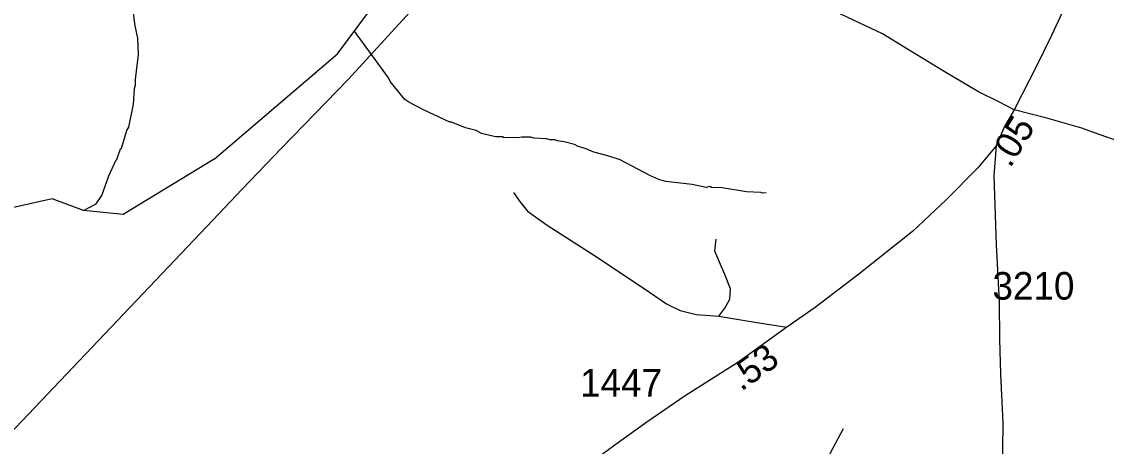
# Model space of a CAD drawing. Extents: x 1547597 to 1699558, y 810033 to 920809.
# Drawn here: x 1593314 to 1598233, y 880561 to 882486 of the extents above; entities that cross this region are included whole.
import ezdxf

# ---------------------------------------------------------------- set-up
doc = ezdxf.new("R2010")
doc.units = 0
for name, color, linetype in [('Exist Hydrographic Creek Single Shore', 7, 'Continuous'), ('Exist Hydrographic Misc Water Feature', 7, 'Continuous'), ('Exist Road Non-System Type 51', 7, 'Continuous'), ('Exist Road Secondary Mileage Hundredths English Label', 7, 'Continuous'), ('Exist Road Secondary Type 51 Attributed', 7, 'Continuous'), ('Exist Road Secondary Type 51 Number Label', 7, 'Continuous'), ('Exist Utilities Electrical Transmission Line', 7, 'Continuous')]:
    doc.layers.add(name, color=color, linetype=linetype)

msp = doc.modelspace()

# ---------------------------------------------------------------- linework, layer by layer
at = {"layer": 'Exist Hydrographic Creek Single Shore'}
for points in [[(1594187.7, 881861.8), (1594746.6, 882339.6), (1594983.6, 882659.8), (1595044.6, 882819.4), (1595315.6, 883138.9), (1595428.6, 883487.9), (1595969.1, 884179.6), (1596114.7, 884695.1), (1596193.9, 885183.4), (1596366.1, 885799.3), (1596375.1, 886314.1)], [(1594187.7, 881861.8), (1593774.6, 881610.9), (1593594.9, 881630.2), (1593452.5, 881682.2), (1592972.6, 881575.9), (1592470.6, 881427.1), (1591866.6, 881163.7), (1591683.6, 881190.4), (1591526.6, 881259.2), (1591117.8, 881560.8), (1590746.3, 882107), (1590660.1, 882244.9), (1590503.1, 882356.4), (1590267.6, 882420.6), (1589867.3, 882354.7)], [(1596667.6, 879444.6), (1596649.4, 879560), (1596571.5, 879569.7), (1596547.1, 879764.6), (1596595.8, 879871.9), (1596683.6, 880071.2), (1596921.6, 880417.7), (1597041.6, 880641.8)]]:
    msp.add_lwpolyline(points, dxfattribs=at)
at = {"layer": 'Exist Hydrographic Misc Water Feature'}
for points in [[(1593594.9, 881630.2), (1593651.5, 881659.7), (1593677.9, 881697.3), (1593709.1, 881786.5), (1593741.5, 881856.4), (1593745.9, 881860.4), (1593761.6, 881908.6), (1593766.6, 881912.2), (1593791.5, 881991.9), (1593799.7, 882007.8), (1593820.9, 882111.4), (1593825.9, 882183.4), (1593830.1, 882199.4), (1593830.4, 882223.4), (1593844.4, 882336.2), (1593840.6, 882411.2), (1593829.2, 882467.4), (1593818.3, 882547.4), (1593802.9, 882603.6), (1593795.6, 882657.8), (1593794.2, 882703.8), (1593784.5, 882739.9), (1593783.5, 882779.2)], [(1596690, 881709.6), (1596673.9, 881707.9), (1596666, 881712), (1596602.1, 881715), (1596490.4, 881733), (1596442.5, 881733.8), (1596434.5, 881737.9), (1596418.5, 881734.1), (1596354.8, 881747.2), (1596235, 881761.3), (1596203.1, 881769.8), (1596163.5, 881788.4), (1596028.7, 881858.7), (1595973.1, 881877.6), (1595909.3, 881894.8), (1595869.6, 881911.4), (1595837.7, 881919.9), (1595821.9, 881928.2), (1595774.2, 881941), (1595742.2, 881945.5), (1595734.3, 881949.6), (1595710.3, 881950), (1595694.4, 881954.3), (1595638.4, 881957.3), (1595622.5, 881961.5), (1595582.5, 881962.2), (1595566.5, 881958.5), (1595558.6, 881960.6), (1595502.6, 881959.6), (1595494.7, 881963.7), (1595462.7, 881964.3), (1595398.9, 881979.4), (1595375.1, 881991.8), (1595327.4, 882004.5), (1595263.8, 882029.6), (1595255.8, 882029.7), (1595136.8, 882085.7), (1595069.3, 882120.8), (1595051.6, 882133.1), (1594984.9, 882214.2), (1594977.1, 882230.4), (1594823.1, 882443)]]:
    msp.add_lwpolyline(points, dxfattribs=at)
at = {"layer": 'Exist Road Non-System Type 51'}
for points in [[(1595544.8, 881710.6), (1595572.5, 881672.3), (1595607.9, 881626.1), (1595697.5, 881563.2), (1595912.2, 881425.6), (1596136.9, 881275.8), (1596238.2, 881206.9), (1596300, 881176.4), (1596373.7, 881157.9), (1596475.6, 881151)], [(1596475.6, 881151), (1596503.9, 881186.7), (1596526.2, 881227.4), (1596528.5, 881274.6), (1596503.2, 881338.8), (1596479.5, 881394.9), (1596458, 881445.1), (1596464.5, 881499)], [(1596475.6, 881151), (1596639.3, 881123.7), (1596785.1, 881100.5)]]:
    msp.add_lwpolyline(points, dxfattribs=at)
at = {"layer": 'Exist Road Secondary Type 51 Attributed'}
for points in [[(1598138.2, 883928.7), (1598144.3, 883785.9), (1598140.2, 883600.3), (1598144.3, 883451.3), (1598154.5, 883265), (1598152.9, 883049.1), (1598134.2, 882837.2), (1598117.9, 882739.3), (1598074.4, 882616.2), (1597985, 882423.1), (1597918.8, 882287), (1597816.2, 882086.1)], [(1597816.2, 882086.1), (1597745.7, 882122.2), (1597653.9, 882167), (1597505.1, 882254.8), (1597331.9, 882360.9), (1597217.7, 882430.2), (1596981.3, 882542.4), (1596740.2, 882657.9), (1596454.8, 882755.9), (1596253, 882817.1), (1596026.8, 882900.7), (1595814.2, 882993.1), (1595566.3, 883084.8), (1595402.4, 883133.3), (1595203.1, 883202.3), (1595061.2, 883244.5), (1594919.4, 883290.5), (1594772.1, 883371.1)], [(1597816.2, 882086.1), (1597772.2, 882010.5), (1597734.2, 881922.2)], [(1600730.5, 880607), (1600618.4, 880660.1), (1600532.8, 880707), (1600402.4, 880804.9), (1600235.2, 880927.3), (1600139.4, 881025.2), (1600021.2, 881121.1), (1599941.7, 881178.2), (1599838.9, 881253.2), (1599659.5, 881375.6), (1599474.7, 881470.8), (1599301.4, 881562.6), (1599193.5, 881617.5), (1598959.3, 881729.3), (1598692.2, 881811.1), (1598451.7, 881884.6), (1598288.6, 881943.7), (1598196.9, 881976.3), (1598122.1, 882002.9), (1597963.1, 882048.7), (1597816.2, 882086.1)], [(1597734.2, 881922.2), (1597651.4, 881823.1), (1597509.2, 881678.8), (1597354.3, 881534.6), (1597110.8, 881341.6), (1596913.6, 881189.3), (1596785.1, 881100.5), (1596562, 880940.3), (1596323.7, 880789), (1596148.9, 880670), (1596004.8, 880565.4), (1595889.6, 880480.7), (1595713.6, 880353.6), (1595529, 880261.1), (1595444.8, 880224)], [(1597734.2, 881922.2), (1597722.8, 881787.3), (1597734.4, 881473.3), (1597748, 881215), (1597748.8, 881047.1), (1597753.4, 880887.1), (1597763.7, 880667.2), (1597761.3, 880430.4), (1597773.4, 880158.8), (1597788.2, 879879.7), (1597802.6, 879647.1), (1597826, 879498.2), (1597860.2, 879290.9), (1597893.9, 879092.9), (1597920.4, 878884.1), (1597930.4, 878771.4), (1597917.1, 878685.3), (1597900.5, 878579.2), (1597874.1, 878473.2), (1597852.9, 878360.2), (1597823, 878221), (1597809.5, 878057.3), (1597811.4, 877852.5), (1597811.8, 877643.3)]]:
    msp.add_lwpolyline(points, dxfattribs=at)
at = {"layer": 'Exist Utilities Electrical Transmission Line'}
msp.add_lwpolyline([(1595074.8, 882528.9), (1594795.4, 882224.2), (1594492.3, 881911.7), (1594314.2, 881725.8), (1594181.7, 881585.2), (1591756.7, 879036.3), (1591646.3, 875142), (1590597.3, 874408.7), (1590660.9, 873411.3), (1590633.8, 873059.7), (1590510, 871286.5), (1590671.8, 869193.1), (1591400.6, 867299.4), (1591680.4, 866599), (1590226.6, 861827.8), (1590099.7, 859136.4), (1590298, 857488.7)], dxfattribs=at)

# ---------------------------------------------------------------- texts
at = {"layer": 'Exist Road Secondary Mileage Hundredths English Label'}
for s, rotation, p in [('.05', 58.5123, (1597797.5, 881818.6)), ('.53', 35.6656, (1596577.2, 880807.4))]:
    msp.add_text(s, height=120, rotation=rotation, dxfattribs=at).set_placement(p)
at = {"layer": 'Exist Road Secondary Type 51 Number Label'}
for s, p in [('3210', (1597717, 881225.7)), ('1447', (1595846.5, 880785.9))]:
    msp.add_text(s, height=125, dxfattribs=at).set_placement(p)

doc.saveas('drawing.dxf')
